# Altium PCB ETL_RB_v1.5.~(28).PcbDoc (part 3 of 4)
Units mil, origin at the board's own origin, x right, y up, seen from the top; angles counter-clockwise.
Board outline 5129.92 x 2224.41 mil, 8 copper layers (Top Layer, plane 1, M1, plane 2, plane 3, M2, plane 4, Bottom Layer), stack 36.907 mil thick; 212 components, 186 nets, 1961 pads, 978 vias.
Unrouted connection lines stored in the file: 395.
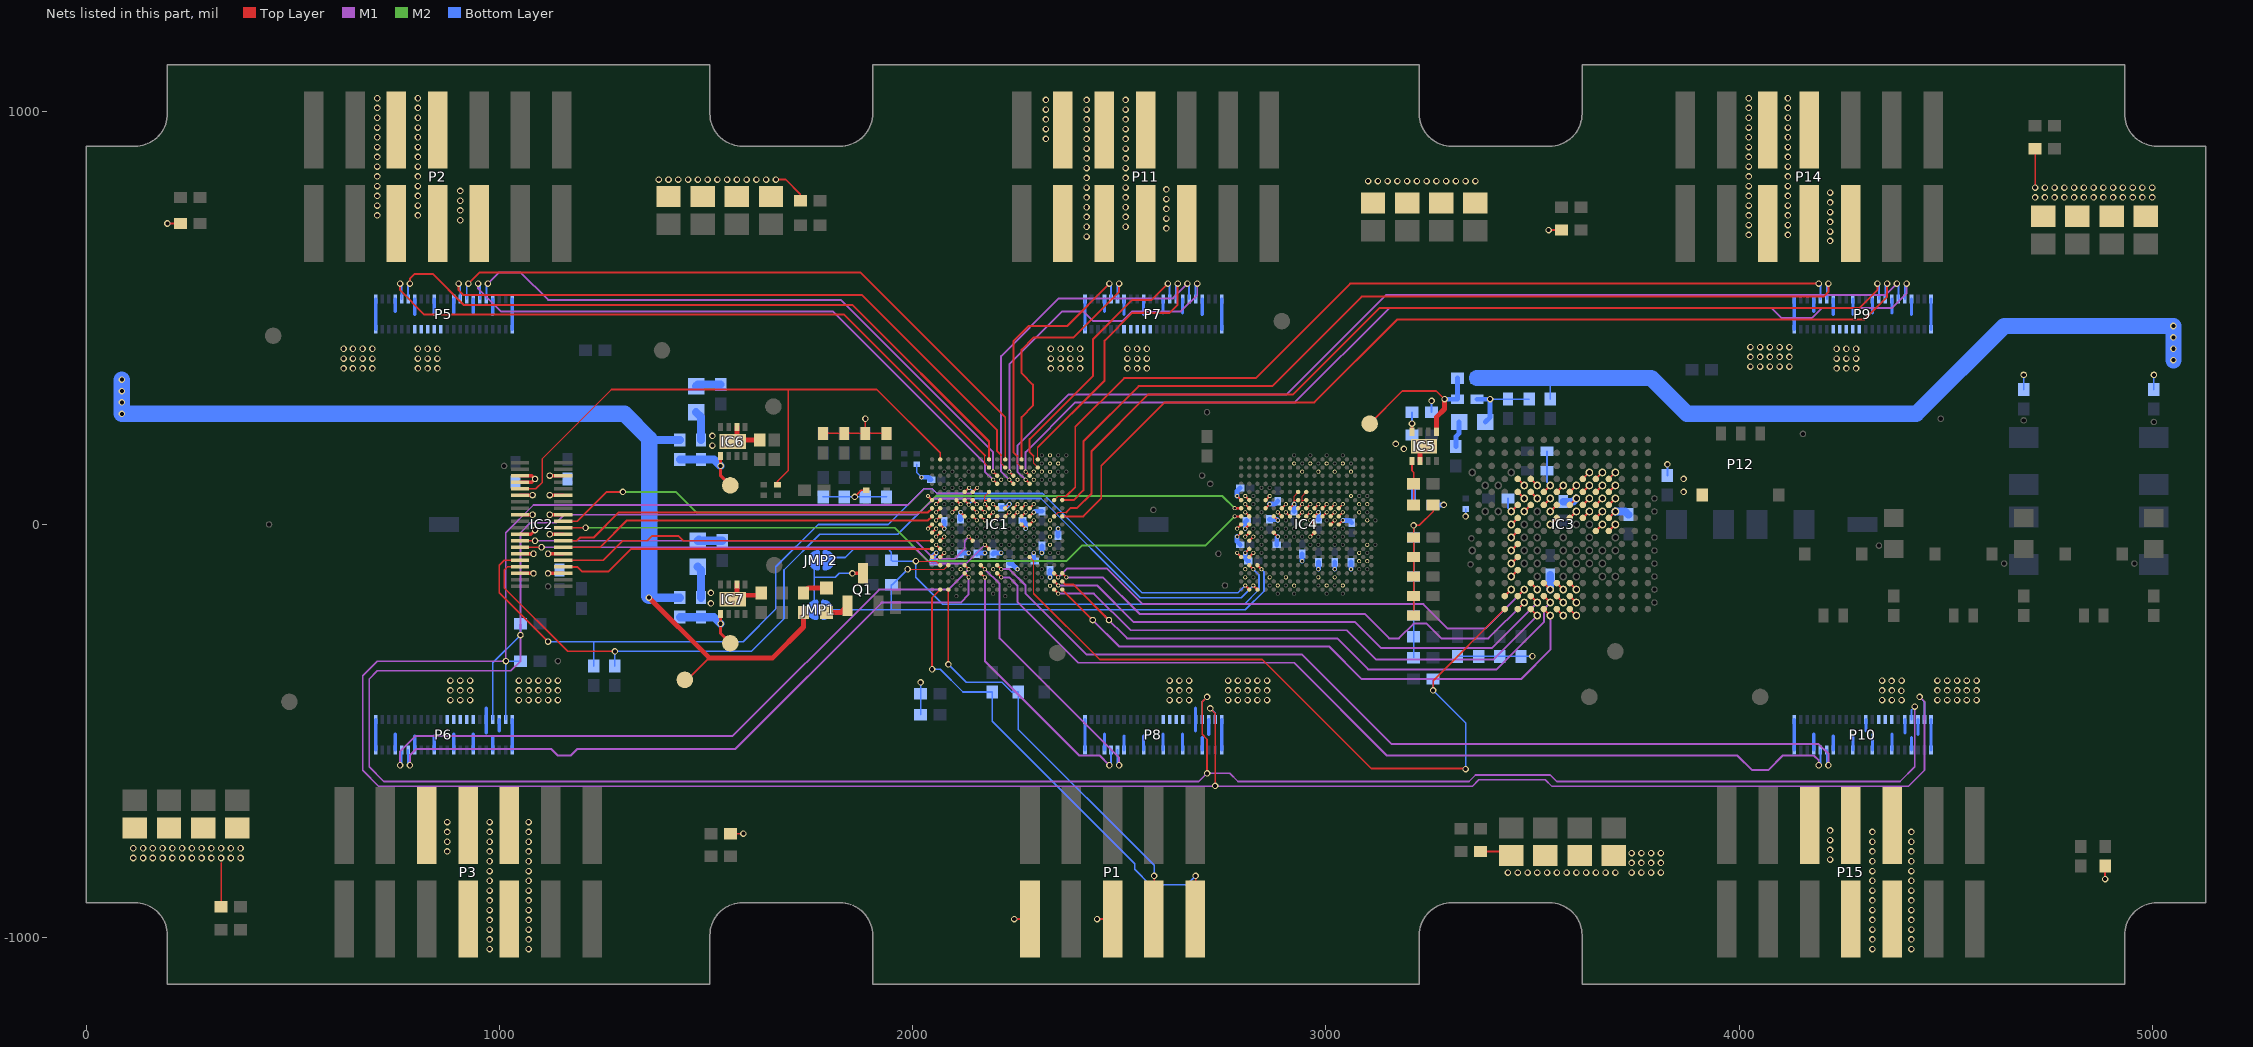
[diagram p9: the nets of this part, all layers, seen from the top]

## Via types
v1: diameter 15.75, hole 9.84, Top Layer to Bottom Layer, 978 vias

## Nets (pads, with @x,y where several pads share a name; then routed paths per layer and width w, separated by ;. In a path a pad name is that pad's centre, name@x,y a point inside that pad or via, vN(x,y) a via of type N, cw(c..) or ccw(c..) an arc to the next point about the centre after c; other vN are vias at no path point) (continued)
EDIN30N: IC1.H17 P9.34 | length 2332.9
  Top Layer w4.72: IC1.H17@2362.2,19.69 2413.39,19.68 2456.69,62.99 2456.69,141.73 2610.24,295.28 2972.44,295.28 3173.23,496.06 4303.15,496.06 4358.27,551.18 v1(4358.27,582.68)
  Bottom Layer w4.72: P9.34@4354.33,545.28 4354.33,578.74 v1(4358.27,582.68)
EDIN30P: IC1.H16 P9.33 | length 2333.5
  Top Layer w3: IC1.H16@2342.52,19.69 2352.36,29.53 2372.05,29.53
  Top Layer w4.72: 2372.05,29.53 2381.89,39.37 2397.64,39.37 2433.07,74.8 2433.07,177.17 2570.87,314.96 2921.26,314.96 3129.92,523.62 4291.34,523.62 4334.65,566.93 v1(4334.65,582.68)
  Bottom Layer w4.72: v1(4334.65,582.68) 4338.58,578.74 P9.33@4338.58,545.28
EDIN32N: IC1.F17 P9.25 | length 2191
  Top Layer w4.72: IC1.F17@2362.2,59.06 2389.76,59.06 2413.39,82.68 2413.39,200.79 2547.24,334.65 2870.08,334.65 3086.61,551.18 4204.72,551.18 4216.54,562.99 v1(4216.54,582.68)
  Bottom Layer w4.72: P9.25@4212.6,545.28 4212.6,578.74 v1(4216.54,582.68)
EDIN32P: IC1.F16 P9.24 | length 2191.6
  Top Layer w3: IC1.F16@2342.52,59.06 2352.36,68.9 2372.05,68.9
  Top Layer w4.72: 2372.05,68.9 2393.7,90.55 2393.7,236.22 2511.81,354.33 2830.71,354.33 3059.06,582.68 v1(4192.91,582.68)
  Bottom Layer w4.72: v1(4192.91,582.68) 4196.85,578.74 P9.24@4196.85,545.28
EDIN40N: IC1.A14 P7.34 | length 657.5
  Top Layer w3: IC1.A14@2303.15,157.48 2303.15,187.01
  Top Layer w4.72: 2303.15,187.01 2464.57,348.43 2464.57,444.88 2531.5,511.81 2622.05,511.81 2641.73,531.5 v1(2641.73,582.68)
  Bottom Layer w4.72: P7.34@2637.8,545.28 2637.8,578.74 v1(2641.73,582.68)
EDIN40P: IC1.B14 P7.33 | length 658.4
  Top Layer w3: 2293.31,165.35 2293.31,147.64 IC1.B14@2303.15,137.8
  Top Layer w4.72: 2293.31,165.35 2283.46,175.2 2283.46,206.69 2437.01,360.24 2437.01,448.82 2531.5,543.31 2578.74,543.31 v1(2618.11,582.68)
  Bottom Layer w4.72: v1(2618.11,582.68) 2622.05,578.74 P7.33@2622.05,545.28
EDIN42N: IC1.A12 P7.25 | length 641.4
  Top Layer w4.72: IC1.A12@2263.78,157.48 2263.78,259.84 2291.34,287.4 2291.34,338.58 2263.78,366.14 2263.78,423.23 2293.31,452.76 2389.76,452.76 2500,562.99 v1(2500,582.68)
  Bottom Layer w4.72: P7.25@2496.06,545.28 2496.06,578.74 v1(2500,582.68)
EDIN42P: IC1.B12 P7.24 | length 642.5
  Top Layer w3: 2253.94,165.35 2253.94,147.64 IC1.B12@2263.78,137.8
  Top Layer w4.72: 2253.94,165.35 2244.09,175.2 2244.09,442.91 2281.5,480.32 2374.02,480.32 v1(2476.38,582.68)
  Bottom Layer w4.72: v1(2476.38,582.68) 2480.31,578.74 P7.24@2480.31,545.28
EDIN50N: IC1.A10 P5.34 | length 1597.2
  Top Layer w4.72: v1(925.2,582.68) 952.76,610.24 1874.02,610.24 2224.41,259.84 IC1.A10@2224.41,157.48
  Bottom Layer w4.72: P5.34@921.26,545.28 921.26,578.74 v1(925.2,582.68)
EDIN50P: IC1.B10 P5.33 | length 1596.9
  Top Layer w3: 2214.57,167.32 2214.57,147.64 IC1.B10@2224.41,137.8
  Top Layer w4.72: v1(901.57,582.68) 901.57,566.93 913.39,555.12 1877.95,555.12 2204.72,228.35 2204.72,177.17 2214.57,167.32
  Bottom Layer w4.72: v1(901.57,582.68) 905.51,578.74 P5.33@905.51,545.28
EDIN52N: IC1.A8 P5.25 | length 1668.6
  Top Layer w4.72: v1(783.46,582.68) 783.46,594.49 795.28,606.3 838.58,606.3 913.39,531.5 1854.33,531.5 2185.04,200.79 IC1.A8@2185.04,157.48
  Bottom Layer w4.72: P5.25@779.53,545.28 779.53,578.74 v1(783.46,582.68)
EDIN52P: IC1.B8 P5.24 | length 1669.3
  Top Layer w3: 2175.2,167.32 2175.2,147.64 IC1.B8@2185.04,137.8
  Top Layer w4.72: v1(759.84,582.68) 759.84,566.93 818.9,507.87 1834.65,507.87 2175.2,167.32
  Bottom Layer w4.72: v1(759.84,582.68) 763.78,578.74 P5.24@763.78,545.28
EDOUT00N: IC1.R5 P6.36 pad.1@2135.83,-127.95 | length 1644.8
  Top Layer w5.12: IC1.R5@2125.98,-118.11 pad.1@2135.83,-127.95
  M1 w4.72: v1(783.46,-582.68) 783.46,-559.06 799.21,-543.31 1125.98,-543.31 1141.73,-559.06 1173.23,-559.06 1188.98,-543.31 1570.87,-543.31 1925.2,-188.98 2116.14,-188.98 2135.83,-169.29 pad.1@2135.83,-127.95
  Bottom Layer w4.72: P6.36@779.53,-545.28 779.53,-578.74 v1(783.46,-582.68)
EDOUT00P: IC1.P5 P6.37 pad.1@2135.83,-108.27 | length 1645
  Top Layer w5.12: IC1.P5@2125.98,-98.42 pad.1@2135.83,-108.27
  M1 w4.72: v1(759.84,-582.68) 759.84,-549.21 797.24,-511.81 1564.96,-511.81 1919.29,-157.48 2086.61,-157.48 pad.1@2135.83,-108.27
  Bottom Layer w4.72: v1(759.84,-582.68) 763.78,-578.74 P6.37@763.78,-545.28
EDOUT02N: IC1.R7 P8.37 pad.1@2175.2,-127.95 | length 661.3
  Top Layer w5.12: IC1.R7@2165.35,-118.11 pad.1@2175.2,-127.95
  M1 w5.12: pad.1@2175.2,-127.95 2175.2,-330.71 2403.54,-559.06 2452.76,-559.06 v1(2476.38,-582.68)
  Bottom Layer w4.72: v1(2476.38,-582.68) 2480.31,-578.74 P8.37@2480.31,-545.28
EDOUT02P: IC1.P7 P8.36 pad.1@2175.2,-108.27 | length 661.9
  Top Layer w5.12: IC1.P7@2165.35,-98.42 pad.1@2175.2,-108.27
  M1 w4.72: pad.1@2175.2,-108.27 2210.63,-143.7 2210.63,-275.59 2468.5,-533.46 2500,-564.96 v1(2500,-582.68)
  Bottom Layer w4.72: P8.36@2496.06,-545.28 2496.06,-578.74 v1(2500,-582.68)
EDOUT10N: IC1.R9 P10.37 pad.1@2214.57,-127.95 | length 2279
  Top Layer w5.12: IC1.R9@2204.72,-118.11 pad.1@2214.57,-127.95
  M1 w4.72: pad.1@2214.57,-127.95 2234.25,-127.95 2253.94,-147.64 2253.94,-187.01 2401.57,-334.65 2923.23,-334.65 3147.64,-559.06 3996.06,-559.06 4031.5,-594.49 4070.87,-594.49 4106.3,-559.06 4181.1,-559.06 4192.91,-570.87 v1(4192.91,-582.68)
  Bottom Layer w4.72: v1(4192.91,-582.68) 4196.85,-578.74 P10.37@4196.85,-545.28
EDOUT10P: IC1.P9 P10.36 pad.1@2214.57,-108.27 | length 2279.1
  Top Layer w5.12: IC1.P9@2204.72,-98.42 pad.1@2214.57,-108.27
  M1 w4.72: pad.1@2214.57,-108.27 2234.25,-108.27 2273.62,-147.64 2273.62,-167.32 2421.26,-314.96 2942.91,-314.96 3159.45,-531.5 4192.91,-531.5 4216.54,-555.12 v1(4216.54,-582.68)
  Bottom Layer w4.72: P10.36@4212.6,-545.28 4212.6,-578.74 v1(4216.54,-582.68)
EDOUT20N: IC1.C13 P9.37 pad.1@2273.62,127.95 | length 2434.3
  Top Layer w5.12: pad.1@2273.62,127.95 IC1.C13@2283.46,118.11
  M1 w4.72: pad.1@2273.62,127.95 2273.62,175.2 2393.7,295.28 2925.2,295.28 3153.54,523.62 4078.74,523.62 4102.36,500 4177.17,500 4200.79,523.62 4370.08,523.62 4405.51,559.06 v1(4405.51,582.68)
  Bottom Layer w4.72: P9.37@4401.57,545.28 4401.57,578.74 v1(4405.51,582.68)
EDOUT20P: IC1.D13 P9.36 pad.1@2273.62,108.27 | length 2434
  Top Layer w5.12: pad.1@2273.62,108.27 IC1.D13@2283.46,98.43
  M1 w4.72: pad.1@2273.62,108.27 2253.94,127.95 2253.94,190.94 2377.95,314.96 2905.51,314.96 3145.67,555.12 4354.33,555.12 v1(4381.89,582.68)
  Bottom Layer w4.72: v1(4381.89,582.68) 4385.83,578.74 P9.36@4385.83,545.28
EDOUT22N: IC1.C11 P7.37 pad.1@2234.25,127.95 | length 884
  Top Layer w5.12: pad.1@2234.25,127.95 IC1.C11@2244.09,118.11
  M1 w4.72: pad.1@2234.25,127.95 2234.25,387.79 2362.2,515.75 2413.39,515.75 2437.01,492.13 2507.87,492.13 2531.5,515.75 2649.61,515.75 2688.98,555.12 v1(2688.98,582.68)
  Bottom Layer w4.72: P7.37@2685.04,545.28 2685.04,578.74 v1(2688.98,582.68)
EDOUT22P: IC1.D11 P7.36 pad.1@2234.25,108.27 | length 883.7
  Top Layer w5.12: pad.1@2234.25,108.27 IC1.D11@2244.09,98.43
  M1 w4.72: pad.1@2234.25,108.27 2214.57,127.95 2214.57,407.48 2354.33,547.24 2629.92,547.24 v1(2665.35,582.68)
  Bottom Layer w4.72: v1(2665.35,582.68) 2669.29,578.74 P7.36@2669.29,545.28
EDOUT30N: IC1.C9 P5.37 pad.1@2194.88,127.95 | length 1514.3
  Top Layer w5.12: pad.1@2194.88,127.95 IC1.C9@2204.72,118.11
  M1 w4.72: v1(972.44,582.68) 1000,610.24 1051.18,610.24 1118.11,543.31 1826.77,543.31 2194.88,175.2 pad.1@2194.88,127.95
  Bottom Layer w4.72: P5.37@968.5,545.28 968.5,578.74 v1(972.44,582.68)
EDOUT30P: IC1.D9 P5.36 pad.1@2194.88,108.27 | length 1514
  Top Layer w5.12: pad.1@2194.88,108.27 IC1.D9@2204.72,98.43
  M1 w4.72: v1(948.82,582.68) 948.82,570.87 1003.94,515.75 1807.09,515.75 2175.2,147.64 2175.2,127.95 pad.1@2194.88,108.27
  Bottom Layer w4.72: v1(948.82,582.68) 952.76,578.74 P5.36@952.76,545.28
GBT_RESET_B: IC1.N13 IC3.M14 R107.2 | length 1833.8
  Top Layer w3: IC1.N13@2283.46,-78.74 2293.31,-88.58 2293.31,-167.32
  Top Layer w4: 2293.31,-167.32 2452.76,-326.77 2846.46,-326.77 3110.24,-590.55 3338.58,-590.55 v1(3338.58,-591.98) ; v1(3259.84,-401.57) 3259.84,-377.95 IC3.M14@3433.07,-204.72
  Bottom Layer w4: R107.2@3259.84,-374.02 v1(3259.84,-401.57) 3338.58,-480.32 v1(3338.58,-591.98)
GND: C105.2 C106.2 C107.2 C108.2 C109.2 C111.2 C112.2 C113.2 C114.2 C115.2 C116.2 C117.2 C118.2 C119.2 C120.2 C121.2 C122.2 C123.2 C124.2 C125.2 C126.2 C127.2 C128.2 C129.2 C130.2 C131.2 C132.2 C133.2 C134.2 C135.2 C136.2 C138.2 C139.2 C140.2 C141.2 C150.2 C151.2 C152.2 C153.2 C154.2 C155.2 C160.2 C162.2 C163.2 C164.2 C165.2 C166.2 C167.2 C168.2 C169.2 C201.1 C202.1 C203.1 C204.1 C205.1 C206.1 C207.1 C208.1 C209.1 C210.1 C211.1 C212.1 C213.1 C214.1 C218.2 C219.2 C220.2 C221.2 C222.2 C223.2 C224.2 C225.2 C226.2 C227.2 C228.2 C229.2 C230.2 C231.2 C232.2 C233.2 IC1.E8 IC1.F1 IC1.F2 IC1.F4 IC1.F8 IC1.G2 IC1.G4 IC1.G6 IC1.G7 IC1.G8 IC1.G9 IC1.G10 IC1.G11 IC1.G12 IC1.G13 IC1.H2 IC1.H5 IC1.H6 IC1.H7 IC1.H8 IC1.H9 IC1.H10 IC1.H11 IC1.H12 IC1.H13 IC1.J1 IC1.J2 IC1.J12 IC1.J13 IC1.K1 IC1.K2 IC1.L2 IC1.M2 IC1.N1 IC1.N2 IC2.5 IC2.6 IC2.11 IC2.12 IC2.17 IC2.18 IC2.23 IC2.24 IC2.29 IC2.30 IC2.34 IC2.35 IC2.36 IC3.D4 IC3.D5 IC3.D6 IC3.D7 IC3.D8 IC3.E4 IC3.E5 IC3.E6 IC3.E7 IC3.E8 IC3.F4 IC3.F5 IC3.F6 IC3.F7 IC3.G5 IC3.G6 IC3.G7 IC3.G12 IC3.G13 IC3.G14 IC3.H5 IC3.H6 IC3.H7 IC3.H12 IC3.H13 IC3.H14 IC3.J5 IC3.J6 IC3.J12 IC3.K4 IC3.K5 IC3.K6 IC3.K12 IC3.L4 IC3.L5 IC3.L6 IC3.L7 IC3.L8 IC3.L9 IC3.L10 IC3.L11 IC3.M13 IC4.E8 IC4.E9 IC4.F1 IC4.F2 IC4.F4 IC4.F8 IC4.F9 IC4.G2 IC4.G4 IC4.G6 IC4.G7 IC4.G8 IC4.G9 IC4.G10 IC4.G11 IC4.G12 IC4.G13 IC4.H2 IC4.H5 IC4.H6 IC4.H7 IC4.H8 IC4.H9 IC4.H10 IC4.H11 IC4.H12 IC4.H13 IC4.J1 IC4.J2 IC4.J10 IC4.J12 IC4.J13 IC4.K1 IC4.K2 IC4.K5 IC4.K10 IC4.L2 IC4.M2 IC4.N1 IC4.N2 IC5.6 IC5.9 IC6.6 IC6.9 IC7.6 IC7.9 JMP1.1 JMP2.1 P1.6 P1.10 P2.5 P2.6 P2.7 P2.8 P2.9 P3.5 P3.6 P3.7 P3.8 P3.9 P5.11 P5.12 P5.13 P5.14 P5.15 P5.23 P5.26 P5.29 P5.32 P5.35 P5.38 P5.41 P5.42 P5.43 P5.44 P6.11 P6.12 P6.13 P6.14 P6.15 P6.17 P6.19 P6.23 P6.26 P6.29 P6.32 P6.35 P6.38 P6.41 P6.42 P6.43 P6.44 P7.11 P7.12 P7.13 P7.14 P7.15 P7.23 P7.26 P7.29 P7.32 P7.35 P7.38 P7.41 P7.42 P7.43 P7.44 P8.12 P8.13 P8.14 P8.15 P8.17 P8.19 P8.23 P8.26 P8.29 P8.32 P8.35 P8.38 P8.41 P8.42 P8.43 P8.44 P9.11 P9.12 P9.13 P9.14 P9.15 P9.23 P9.26 P9.29 P9.32 P9.35 P9.38 P9.41 P9.42 P9.43 P9.44 P10.11 P10.13 P10.14 P10.15 P10.17 P10.19 P10.23 P10.26 P10.29 P10.32 P10.35 P10.38 P10.41 P10.42 P10.43 P10.44 P11.5 P11.6 P11.7 P11.8 P11.9 P12.4 P14.5 P14.6 P14.7 P14.8 P14.9 P15.5 P15.6 P15.7 P15.8 P15.9 pad.1@1080.71,23.62 pad.1@1080.71,70.87 pad.1@1082.68,-70.87 pad.1@1082.68,-118.11 pad.1@1086.61,110.24 pad.1@1086.61,-13.78 pad.1@1118.11,-70.87 pad.1@1118.11,-118.11 pad.1@1122.05,23.62 pad.1@1122.05,70.87 pad.1@1122.05,118.11 pad.1@1122.05,-23.62 pad.1@2021.65,114.17 pad.1@2037.4,68.9 pad.1@2037.4,-9.84 pad.1@2057.09,9.84 pad.1@2057.09,29.53 pad.1@2057.09,49.21 pad.1@2057.09,-9.84 pad.1@2057.09,-29.53 pad.1@2057.09,-49.21 pad.1@2057.09,-68.9 pad.1@2076.77,-9.84 pad.1@2076.77,-29.53 pad.1@2076.77,-68.9 pad.1@2096.46,29.53 pad.1@2116.14,29.53 pad.1@2116.14,49.21 pad.1@2116.14,-108.27 pad.1@2135.83,-68.9 pad.1@2155.51,9.84 pad.1@2155.51,29.53 pad.1@2175.2,9.84 pad.1@2175.2,29.53 pad.1@2175.2,49.21 pad.1@2175.2,-68.9 pad.1@2194.88,9.84 pad.1@2194.88,29.53 pad.1@2194.88,49.21 pad.1@2194.88,-108.27 pad.1@2214.57,108.27 pad.1@2214.57,-68.9 pad.1@2234.25,29.53 pad.1@2234.25,49.21 pad.1@2253.94,29.53 pad.1@2253.94,49.21 pad.1@2253.94,108.27 pad.1@2253.94,-108.27 pad.1@2273.62,29.53 pad.1@2273.62,49.21 pad.1@2273.62,-9.84 pad.1@2293.31,9.84 pad.1@2293.31,29.53 pad.1@2293.31,49.21 pad.1@2293.31,108.27 pad.1@2293.31,127.95 pad.1@2293.31,-68.9 pad.1@2312.99,127.95 pad.1@2312.99,-68.9 pad.1@2332.58,-148.45 pad.1@2332.59,127.48 pad.1@2332.68,9.84 pad.1@2332.68,147.64 pad.1@2332.68,167.32 pad.1@2332.68,-9.84 pad.1@2332.68,-29.53 pad.1@2332.68,-49.21 pad.1@2332.68,-127.95 pad.1@2352.36,147.64 pad.1@2352.36,-9.84 pad.1@2785.43,68.9 pad.1@2785.43,-9.84 pad.1@2785.43,-29.53 pad.1@2785.43,-68.9 pad.1@2805.12,29.53 pad.1@2805.12,49.21 pad.1@2805.12,68.9 pad.1@2805.12,-9.84 pad.1@2805.12,-29.53 pad.1@2805.12,-68.9 pad.1@2805.12,-108.27 pad.1@2805.12,-127.95 pad.1@2824.8,-29.53 pad.1@2824.8,-68.9 pad.1@2864.17,49.21 pad.1@2864.17,68.9 pad.1@2864.17,-127.95 pad.1@2883.86,9.84 pad.1@2883.86,29.53 pad.1@2883.86,-29.53 pad.1@2883.86,-147.64 pad.1@2903.54,29.53 pad.1@2903.54,49.21 pad.1@2903.54,-127.95 pad.1@2923.23,49.21 pad.1@2923.23,147.64 pad.1@2923.44,-147.82 pad.1@2942.91,29.53 pad.1@2942.91,49.21 pad.1@2942.91,127.95 pad.1@2942.91,-88.58 pad.1@2962.6,9.84 pad.1@2962.6,29.53 pad.1@2962.6,49.21 pad.1@2962.6,147.64 pad.1@2962.6,-29.53 pad.1@2982.28,29.53 pad.1@2982.28,49.21 pad.1@2982.28,127.95 pad.1@2982.28,-108.27 pad.1@2982.28,-127.95 pad.1@3001.97,29.53 pad.1@3001.97,49.21 pad.1@3001.97,147.64 pad.1@3001.97,-147.64 pad.1@3021.65,9.84 pad.1@3021.65,29.53 pad.1@3021.65,49.21 pad.1@3021.65,127.95 pad.1@3021.65,-108.27 pad.1@3021.65,-127.95 pad.1@3041.34,9.84 pad.1@3041.34,29.53 pad.1@3041.34,49.21 pad.1@3041.34,147.64 pad.1@3041.34,-147.64 pad.1@3061.02,68.9 pad.1@3061.02,127.95 pad.1@3061.02,-108.27 pad.1@3080.71,29.53 pad.1@3080.71,49.21 pad.1@3080.71,-68.9 pad.1@3080.71,-88.58 pad.1@3100.39,9.84 pad.1@3100.39,49.21 pad.1@3100.39,-49.21 pad.1@3100.39,-88.58 pad.1@3448.82,0 pad.1@3448.82,31.5 pad.1@3448.82,-31.5 pad.1@3448.82,-62.99 pad.1@3448.82,-94.49 pad.1@3448.82,-125.98 pad.1@3448.82,-157.48 pad.1@3480.31,31.5 pad.1@3480.31,62.99 pad.1@3480.31,94.49 pad.1@3511.81,62.99 pad.1@3511.81,94.49 pad.1@3511.81,-157.48 pad.1@3543.31,0 pad.1@3543.31,31.5 pad.1@3543.31,62.99 pad.1@3543.31,94.49 pad.1@3543.31,-157.48 pad.1@3574.8,94.49 pad.1@3574.8,-157.48 pad.1@3574.8,-188.98 pad.1@3574.8,-220.47 pad.1@3606.3,31.5 pad.1@3606.3,62.99 pad.1@3606.3,94.49 pad.1@3606.3,-157.48 pad.1@3606.3,-188.98 pad.1@3606.3,-220.47 pad.1@3637.8,31.5 pad.1@3637.8,62.99 pad.1@3637.8,94.49 pad.1@3637.8,125.98 pad.1@3669.29,0 pad.1@3669.29,31.5 pad.1@3669.29,62.99 pad.1@3669.29,94.49 pad.1@3669.29,125.98 pad.1@3700.79,0 pad.1@3700.79,31.5 pad.1@3700.79,62.99 pad.1@3700.79,94.49 pad.1@3700.79,125.98 pad.1@4688.98,362.2 pad.1@5003.94,362.2 Q1.3 R112.2 R115.2 R118.1 R120.1 R122.1 R123.2 R126.2 R132.2 R134.1 R143.1 R146.1 R203.1 R205.1 R207.1 R209.1 R211.1 R213.1 R215.1 R217.1 R219.1 R221.1 R223.1 R225.1 R227.1 R229.1 R233.2 R234.2 R235.2 R236.2 RT1.1 RT2.1 | length 8528
  Top Layer w3: pad.1@2175.2,49.21 2175.2,59.06 ; IC1.F8@2185.04,59.06 2175.2,59.06 ; IC1.E8@2185.04,78.74 2175.2,68.9 2175.2,59.06 ; pad.1@2923.23,49.21 2923.23,59.06 ; IC4.F8@2933.07,59.05 2923.23,59.06 ; IC4.E8@2933.07,78.74 2923.23,68.9 2923.23,59.06 ; pad.1@2942.91,49.21 2942.91,59.05 ; IC4.F9@2952.76,59.05 2942.91,59.05 ; IC4.E9@2952.76,78.74 2942.91,68.9 2942.91,59.05
  Top Layer w4: v1(196.85,728.35) R233.2@228.35,728.35 ; R217.1@326.77,-925.2 326.77,-818.9 ; R234.2@1559.06,-748.03 v1(1590.55,-748.03) ; v1(1669.29,834.65) 1692.91,834.65 1728.35,799.21 R215.1@1728.35,783.46 ; C151.2@1783.46,220.47 C150.2@1834.65,220.47 C109.2@1885.83,220.47 ; v1(1860.24,66.93) 1875.98,82.68 RT1.1@1887.8,82.68 ; v1(1885.83,255.91) C109.2@1885.83,220.47 ; C141.2@1937.01,220.47 C109.2@1885.83,220.47 ; v1(2246.06,-954.72) 2248.03,-954.72 P1.10@2284.25,-954.72 ; v1@2448.82,-954.72 v1(2446.85,-954.72) P1.6@2484.25,-954.72 ; C201.1@3212.6,-220.47 C203.1@3212.6,-173.23 C205.1@3212.6,-125.98 C207.1@3212.6,-78.74 C210.1@3212.6,-31.5 ; R221.1@3374.02,-791.34 3438.98,-791.34 C233.2@3448.82,-801.18 ; v1(3539.37,712.6) R235.2@3570.87,712.6 ; v1(4716.54,814.96) R219.1@4716.54,909.45 ; v1(4885.83,-858.27) R236.2@4885.83,-826.77
  Top Layer w4.02: C210.1@3212.6,-31.5 v1(3212.6,-1.97) 3226.38,-1.97 3259.84,31.5 R112.2@3259.84,47.24
  Top Layer w5.12: pad.1@2037.4,-9.84 IC1.J1@2047.24,0 ; pad.1@2037.4,68.9 IC1.F1@2047.24,59.06 ; IC1.N1@2047.24,-78.74 pad.1@2057.09,-68.9 ; IC1.K1@2047.24,-19.68 pad.1@2057.09,-9.84 ; pad.1@2057.09,-49.21 IC1.M2@2066.93,-59.05 ; pad.1@2057.09,-29.53 IC1.K2@2066.93,-19.68 ; pad.1@2057.09,9.84 IC1.H2@2066.93,19.69 ; pad.1@2057.09,29.53 IC1.G2@2066.93,39.37 ; pad.1@2057.09,49.21 IC1.F2@2066.93,59.06 ; IC1.N2@2066.93,-78.74 pad.1@2076.77,-68.9 ; IC1.L2@2066.93,-39.37 pad.1@2076.77,-29.53 ; IC1.J2@2066.93,0 pad.1@2076.77,-9.84 ; pad.1@2096.46,29.53 IC1.G4@2106.3,39.37 ; IC1.F4@2106.3,59.06 pad.1@2116.14,49.21 ; pad.1@2116.14,29.53 IC1.H5@2125.98,19.69 ; IC1.H6@2145.67,19.69 pad.1@2155.51,9.84 ; IC1.G6@2145.67,39.37 pad.1@2155.51,29.53 ; IC1.H7@2165.35,19.69 pad.1@2175.2,9.84 ; IC1.G7@2165.35,39.37 pad.1@2175.2,29.53 ; pad.1@2175.2,49.21 IC1.G8@2185.04,39.37 ; IC1.H8@2185.04,19.69 pad.1@2194.88,29.53 ; pad.1@2194.88,9.84 IC1.H9@2204.72,19.69 ; pad.1@2194.88,49.21 IC1.G9@2204.72,39.37 ; IC1.H10@2224.41,19.69 pad.1@2234.25,29.53 ; IC1.G10@2224.41,39.37 pad.1@2234.25,49.21 ; IC1.H11@2244.09,19.69 pad.1@2253.94,29.53 ; IC1.G11@2244.09,39.37 pad.1@2253.94,49.21 ; IC1.J12@2263.78,0 pad.1@2273.62,-9.84 ; IC1.H12@2263.78,19.69 pad.1@2273.62,29.53 ; IC1.G12@2263.78,39.37 pad.1@2273.62,49.21 ; IC1.J13@2283.46,0 pad.1@2293.31,9.84 ; IC1.H13@2283.46,19.69 pad.1@2293.31,29.53 ; IC1.G13@2283.46,39.37 pad.1@2293.31,49.21 ; pad.1@2785.43,-68.9 IC4.N1@2795.28,-78.74 ; pad.1@2785.43,-29.53 IC4.K1@2795.28,-19.68 ; pad.1@2785.43,-9.84 IC4.J1@2795.28,0 ; pad.1@2785.43,68.9 IC4.F1@2795.28,59.05 ; pad.1@2805.12,-68.9 IC4.M2@2814.96,-59.05 ; pad.1@2805.12,-29.53 IC4.K2@2814.96,-19.68 ; pad.1@2805.12,-9.84 IC4.J2@2814.96,0 ; pad.1@2805.12,29.53 IC4.H2@2814.96,19.68 ; pad.1@2805.12,49.21 IC4.G2@2814.96,39.37 ; pad.1@2805.12,68.9 IC4.F2@2814.96,59.05 ; IC4.N2@2814.96,-78.74 pad.1@2824.8,-68.9 ; IC4.L2@2814.96,-39.37 pad.1@2824.8,-29.53 ; IC4.G4@2854.33,39.37 pad.1@2864.17,49.21 ; IC4.F4@2854.33,59.05 pad.1@2864.17,68.9 ; IC4.K5@2874.02,-19.68 pad.1@2883.86,-29.53 ; IC4.H5@2874.02,19.68 pad.1@2883.86,9.84 ; pad.1@2883.86,29.53 IC4.H6@2893.7,19.68 ; IC4.G6@2893.7,39.37 pad.1@2903.54,49.21 ; pad.1@2903.54,29.53 IC4.H7@2913.39,19.68 ; IC4.G7@2913.39,39.37 pad.1@2923.23,49.21 ; IC4.H8@2933.07,19.68 pad.1@2942.91,29.53 ; IC4.G8@2933.07,39.37 pad.1@2942.91,49.21 ; IC4.H9@2952.76,19.68 pad.1@2962.6,29.53 ; IC4.G9@2952.76,39.37 pad.1@2962.6,49.21 ; pad.1@2962.6,-29.53 IC4.K10@2972.44,-19.68 ; pad.1@2962.6,9.84 IC4.J10@2972.44,0 ; IC4.H10@2972.44,19.68 pad.1@2982.28,29.53 ; IC4.G10@2972.44,39.37 pad.1@2982.28,49.21 ; IC4.H11@2992.13,19.68 pad.1@3001.97,29.53 ; IC4.G11@2992.13,39.37 pad.1@3001.97,49.21 ; IC4.J12@3011.81,0 pad.1@3021.65,9.84 ; IC4.H12@3011.81,19.68 pad.1@3021.65,29.53 ; IC4.G12@3011.81,39.37 pad.1@3021.65,49.21 ; IC4.J13@3031.5,0 pad.1@3041.34,9.84 ; IC4.H13@3031.5,19.68 pad.1@3041.34,29.53 ; IC4.G13@3031.5,39.37 pad.1@3041.34,49.21 ; IC3.M13@3433.07,-173.23 pad.1@3448.82,-157.48 ; pad.1@3448.82,-125.98 IC3.L11@3464.57,-110.24 ; pad.1@3448.82,-94.49 IC3.L10@3464.57,-78.74 ; pad.1@3448.82,-62.99 IC3.L9@3464.57,-47.24 ; pad.1@3448.82,-31.5 IC3.L8@3464.57,-15.75 ; pad.1@3448.82,0 IC3.L7@3464.57,15.75 ; pad.1@3448.82,31.5 IC3.L6@3464.57,47.24 ; IC3.L5@3464.57,78.74 pad.1@3480.31,62.99 ; IC3.L4@3464.57,110.24 pad.1@3480.31,94.49 ; pad.1@3480.31,31.5 IC3.K6@3496.06,47.24 ; IC3.K12@3496.06,-141.73 pad.1@3511.81,-157.48 ; IC3.K5@3496.06,78.74 pad.1@3511.81,62.99 ; IC3.K4@3496.06,110.24 pad.1@3511.81,94.49 ; IC3.J12@3527.56,-141.73 pad.1@3543.31,-157.48 ; IC3.J6@3527.56,47.24 pad.1@3543.31,62.99 ; IC3.J5@3527.56,78.74 pad.1@3543.31,94.49 ; pad.1@3543.31,0 IC3.H7@3559.05,15.75 ; pad.1@3543.31,31.5 IC3.H6@3559.05,47.24 ; IC3.H14@3559.05,-204.72 pad.1@3574.8,-220.47 ; IC3.H13@3559.05,-173.23 pad.1@3574.8,-188.98 ; IC3.H12@3559.05,-141.73 pad.1@3574.8,-157.48 ; IC3.H5@3559.05,78.74 pad.1@3574.8,94.49 ; IC3.G14@3590.55,-204.72 pad.1@3606.3,-220.47 ; IC3.G13@3590.55,-173.23 pad.1@3606.3,-188.98 ; IC3.G12@3590.55,-141.73 pad.1@3606.3,-157.48 ; IC3.G7@3590.55,15.75 pad.1@3606.3,31.5 ; IC3.G6@3590.55,47.24 pad.1@3606.3,62.99 ; IC3.G5@3590.55,78.74 pad.1@3606.3,94.49 ; IC3.F7@3622.05,15.75 pad.1@3637.8,31.5 ; IC3.F6@3622.05,47.24 pad.1@3637.8,62.99 ; IC3.F5@3622.05,78.74 pad.1@3637.8,94.49 ; IC3.F4@3622.05,110.24 pad.1@3637.8,125.98 ; IC3.E8@3653.54,-15.75 pad.1@3669.29,0 ; IC3.E7@3653.54,15.75 pad.1@3669.29,31.5 ; IC3.E6@3653.54,47.24 pad.1@3669.29,62.99 ; IC3.E5@3653.54,78.74 pad.1@3669.29,94.49 ; IC3.E4@3653.54,110.24 pad.1@3669.29,125.98 ; IC3.D8@3685.04,-15.75 pad.1@3700.79,0 ; IC3.D7@3685.04,15.75 pad.1@3700.79,31.5 ; IC3.D6@3685.04,47.24 pad.1@3700.79,62.99 ; IC3.D5@3685.04,78.74 pad.1@3700.79,94.49 ; IC3.D4@3685.04,110.24 pad.1@3700.79,125.98
  Top Layer w7.87: IC2.6@1050,-118.11 pad.1@1082.68,-118.11 ; IC2.12@1050,-70.87 pad.1@1082.68,-70.87 ; IC2.18@1050,-23.62 1076.77,-23.62 pad.1@1086.61,-13.78 ; IC2.24@1050,23.62 pad.1@1080.71,23.62 ; IC2.30@1050,70.87 pad.1@1080.71,70.87 ; IC2.34@1050,102.36 1078.74,102.36 pad.1@1086.61,110.24 1078.74,118.11 IC2.36@1050,118.11 ; pad.1@1118.11,-118.11 IC2.5@1154.72,-118.11 ; pad.1@1118.11,-70.87 IC2.11@1154.72,-70.87 ; pad.1@1122.05,-23.62 IC2.17@1154.72,-23.62 ; pad.1@1122.05,23.62 IC2.23@1154.72,23.62 ; pad.1@1122.05,70.87 IC2.29@1154.72,70.87 ; pad.1@1122.05,118.11 IC2.35@1154.72,118.11 ; v1(1854.33,-118.11) Q1.3@1879.92,-118.11
  Top Layer w11.81: IC7.9@1564.96,-181.1 IC7.9@1574.8,-171.26 ; IC7.6@1574.8,-145.67 IC7.9@1574.8,-171.26 ; IC6.6@1574.8,236.22 1574.8,210.63 1569.88,205.71 1570.87,204.72 R115.2@1629.92,204.72 ; R123.2@1633.86,-165.35 1635.83,-165.35 1629.92,-171.26 IC7.9@1574.8,-171.26 ; IC5.6@3228.35,153.54 3228.35,179.13 IC5.9@3238.19,188.98
  Bottom Layer w4: 1761.81,-93.14 1761.81,-96.46 1761.81,-103.66 1761.81,-127.95 ; 1767.72,-194.88 1761.81,-188.98 1761.81,-187.91 1761.81,-127.95 ; R122.1@1783.46,66.93 R120.1@1834.65,66.93 R118.1@1885.83,66.93 R134.1@1937.01,66.93 ; v1(1854.33,-118.11) 1822.83,-118.11 1812.99,-127.95 1761.81,-127.95 ; R146.1@2009.84,145.67 2009.84,125.98 pad.1@2021.65,114.17 ; R132.2@2019.69,-460.63 v1(2019.69,-381.89) ; R203.1@3212.6,-322.83 R205.1@3212.6,-271.65 C202.1@3212.6,-220.47 C204.1@3212.6,-173.23 C206.1@3212.6,-125.98 C209.1@3212.6,-78.74 C208.1@3212.6,-31.5 ; R126.2@3255.91,271.65 v1(3255.91,299.21) ; R207.1@3318.9,-318.9 R209.1@3370.08,-318.9 R211.1@3421.26,-318.9 R213.1@3472.44,-318.9 v1(3500,-318.9) ; v1(3338.58,19.68) RT2.1@3338.58,37.4 ; v1(3397.64,303.15) C214.1@3440.94,303.15 R229.1@3492.13,303.15 ; C213.1@3535.43,177.17 C212.1@3535.43,129.92 3535.43,102.36 pad.1@3543.31,94.49
  Bottom Layer w4.02: C208.1@3212.6,-31.5 v1(3212.6,-1.97) ; C211.1@3440.94,62.99 3440.94,39.37 pad.1@3448.82,31.5 ; R227.1@3826.77,118.11 v1(3826.77,145.67) ; R225.1@4688.98,326.77 pad.1@4688.98,362.2 ; R223.1@5003.94,326.77 pad.1@5003.94,362.2
  Bottom Layer w7.87: P6.44@700.79,-545.28 P6.41@700.79,-472.44 ; P5.42@700.79,472.44 P5.43@700.79,545.28 ; P6.38@748.03,-545.28 748.03,-507.87 ; 748.03,515.75 P5.23@748.03,545.28 ; P6.35@795.28,-545.28 795.28,-511.81 ; 795.28,507.87 P5.26@795.28,545.28 ; P6.32@842.52,-545.28 842.52,-511.81 ; 842.52,507.87 P5.29@842.52,545.28 ; P6.29@889.76,-545.28 889.76,-507.87 ; 889.76,511.81 P5.32@889.76,545.28 ; P6.26@937.01,-545.28 937.01,-507.87 ; 937.01,511.81 P5.35@937.01,545.28 ; 968.5,-503.94 P6.17@968.5,-472.44 968.5,-444.88 ; P6.23@984.25,-545.28 984.25,-515.75 ; 984.25,507.87 P5.38@984.25,545.28 ; 1000,-500 P6.19@1000,-472.44 ; P6.43@1031.5,-545.28 P6.42@1031.5,-472.44 ; P5.41@1031.5,472.44 P5.44@1031.5,545.28 ; P8.44@2417.32,-545.28 P8.41@2417.32,-472.44 ; P7.42@2417.32,472.44 P7.43@2417.32,545.28 ; P8.38@2464.57,-545.28 2464.57,-507.87 ; 2464.57,515.75 P7.23@2464.57,545.28 ; P8.35@2511.81,-545.28 2511.81,-511.81 ; 2511.81,507.87 P7.26@2511.81,545.28 ; P8.32@2559.06,-545.28 2559.06,-511.81 ; 2559.06,507.87 P7.29@2559.06,545.28 ; P8.29@2606.3,-545.28 2606.3,-507.87 ; 2606.3,511.81 P7.32@2606.3,545.28 ; P8.26@2653.54,-545.28 2653.54,-507.87 ; 2653.54,511.81 P7.35@2653.54,545.28 ; 2685.04,-500 P8.17@2685.04,-472.44 2685.04,-444.88 ; P8.23@2700.79,-545.28 2700.79,-515.75 ; 2700.79,507.87 P7.38@2700.79,545.28 ; 2716.54,-507.87 P8.19@2716.54,-472.44 ; P8.43@2748.03,-545.28 P8.42@2748.03,-472.44 ; P7.41@2748.03,472.44 P7.44@2748.03,545.28 ; P10.44@4133.86,-545.28 P10.41@4133.86,-472.44 ; P9.42@4133.86,472.44 P9.43@4133.86,545.28 ; P10.38@4181.1,-545.28 4181.1,-507.87 ; 4181.1,515.75 P9.23@4181.1,545.28 ; P10.35@4228.35,-545.28 4228.35,-511.81 ; 4228.35,507.87 P9.26@4228.35,545.28 ; P10.32@4275.59,-545.28 4275.59,-511.81 ; 4275.59,507.87 P9.29@4275.59,545.28 ; 4307.09,-500 P10.11@4307.09,-472.44 ; P10.29@4322.83,-545.28 4322.83,-507.87 ; 4322.83,511.81 P9.32@4322.83,545.28 ; P10.26@4370.08,-545.28 4370.08,-507.87 ; 4370.08,511.81 P9.35@4370.08,545.28 ; 4401.57,-503.94 P10.17@4401.57,-472.44 ; P10.23@4417.32,-545.28 4417.32,-515.75 ; 4417.32,507.87 P9.38@4417.32,545.28 ; 4433.07,-507.87 P10.19@4433.07,-472.44 ; P10.43@4464.57,-545.28 P10.42@4464.57,-472.44 ; P9.41@4464.57,472.44 P9.44@4464.57,545.28
  Bottom Layer w11.81: pad.1@2021.65,114.17 2038.98,114.17 C119.2@2044.88,108.27 C119.2@2041.34,108.27 ; C125.2@2050.79,-90.55 2050.79,-75.2 pad.1@2057.09,-68.9 ; pad.1@2076.77,-9.84 C116.2@2076.77,7.48 ; C117.2@2116.14,-71.26 2118.5,-68.9 pad.1@2135.83,-68.9 ; C126.2@2116.14,12.2 pad.1@2116.14,29.53 ; C114.2@2155.51,-71.26 2157.87,-68.9 pad.1@2175.2,-68.9 ; C122.2@2194.88,-71.26 2197.24,-68.9 pad.1@2214.57,-68.9 ; C120.2@2214.57,41.73 2226.77,41.73 pad.1@2234.25,49.21 ; C118.2@2234.25,-94.88 2240.55,-94.88 pad.1@2253.94,-108.27 ; C136.2@2266.14,9.84 2273.62,2.36 pad.1@2273.62,-9.84 ; pad.1@2293.31,-68.9 2293.31,-86.22 C123.2@2295.67,-88.58 ; pad.1@2293.31,29.53 2295.67,31.89 C124.2@2312.99,31.89 ; pad.1@2312.99,-68.9 C115.2@2312.99,-51.57 ; pad.1@2332.68,-127.95 C121.2@2332.68,-110.63 ; C113.2@2352.36,-27.56 C113.2@2352.36,-27.17 pad.1@2352.36,-9.84 ; pad.1@2785.43,-29.53 2785.43,-41.73 C130.2@2792.91,-49.21 ; pad.1@2785.43,68.9 2785.43,81.1 C133.2@2792.91,88.58 ; pad.1@2805.12,-68.9 2805.12,-81.1 C132.2@2812.6,-88.58 ; pad.1@2805.12,-9.84 2805.12,6.3 C164.2@2808.66,9.84 ; C163.2@2864.17,12.2 2881.5,12.2 pad.1@2883.86,9.84 ; pad.1@2864.17,49.21 2876.38,49.21 C167.2@2883.86,56.69 ; C168.2@2881.5,-49.21 2881.5,-31.89 pad.1@2883.86,-29.53 ; pad.1@2923.23,49.21 C129.2@2923.23,31.89 C129.2@2923.62,31.5 ; pad.1@2942.91,-88.58 C128.2@2942.91,-71.26 ; pad.1@2982.28,-108.27 C134.2@2982.28,-90.94 ; C131.2@2982.28,12.2 pad.1@2982.28,29.53 ; pad.1@3021.65,-108.27 C165.2@3021.65,-90.94 ; pad.1@3041.34,9.84 3057.48,9.84 C166.2@3062.99,4.33 ; pad.1@3061.02,-108.27 C135.2@3061.02,-90.94 ; C155.2@3259.84,47.24 v1(3285.43,47.24) ; C105.2@3366.14,303.15 v1(3397.64,303.15) 3397.64,259.84 C107.2@3385.83,248.03
  Bottom Layer w18.9: pad.1@3543.31,-157.48 C138.2@3543.31,-122.05 ; C140.2@3574.8,55.12 3598.43,55.12 pad.1@3606.3,62.99 ; pad.1@3700.79,31.5 3724.41,31.5 C139.2@3732.28,23.62
  Bottom Layer w19.68: C108.2@1476.38,271.65 1488.19,259.84 C106.2@1488.19,204.72 ; C169.2@1480.31,-102.36 1488.19,-110.24 C152.2@1488.19,-177.17
  other v1: 976.38,-1027.56 1070.87,-1027.56 4322.83,-1027.56 4417.32,-1027.56 976.38,-1003.94 1070.87,-1003.94 4322.83,-1003.94 4417.32,-1003.94 976.38,-980.32 1070.87,-980.32 4322.83,-980.32 4417.32,-980.32 976.38,-956.69 1070.87,-956.69 4322.83,-956.69 4417.32,-956.69 976.38,-933.07 1070.87,-933.07 4322.83,-933.07 4417.32,-933.07 976.38,-909.45 1070.87,-909.45 4322.83,-909.45 4417.32,-909.45 976.38,-885.83 1070.87,-885.83 4322.83,-885.83 4417.32,-885.83 976.38,-862.2 1070.87,-862.2 4322.83,-862.2 4417.32,-862.2 3440.94,-842.52 3464.57,-842.52 3488.19,-842.52 3511.81,-842.52 3535.43,-842.52 3559.06,-842.52 3582.68,-842.52 3606.3,-842.52 3629.92,-842.52 3653.54,-842.52 3677.17,-842.52 3700.79,-842.52 3740.16,-842.52 3763.78,-842.52 3787.4,-842.52 3811.02,-842.52 976.38,-838.58 1070.87,-838.58 4322.83,-838.58 4417.32,-838.58 3740.16,-818.9 3763.78,-818.9 3787.4,-818.9 3811.02,-818.9 976.38,-814.96 1070.87,-814.96 4322.83,-814.96 4417.32,-814.96 4220.47,-811.02 114.17,-807.09 137.8,-807.09 161.42,-807.09 185.04,-807.09 208.66,-807.09 232.28,-807.09 255.91,-807.09 279.53,-807.09 303.15,-807.09 326.77,-807.09 350.39,-807.09 374.02,-807.09 3740.16,-795.28 3763.78,-795.28 3787.4,-795.28 3811.02,-795.28 874.02,-791.34 976.38,-791.34 1070.87,-791.34 4322.83,-791.34 4417.32,-791.34 4220.47,-787.4 114.17,-783.46 137.8,-783.46 161.42,-783.46 185.04,-783.46 208.66,-783.46 232.28,-783.46 255.91,-783.46 279.53,-783.46 303.15,-783.46 326.77,-783.46 350.39,-783.46 374.02,-783.46 874.02,-767.72 976.38,-767.72 1070.87,-767.72 4322.83,-767.72 4417.32,-767.72 4220.47,-763.78 874.02,-744.09 976.38,-744.09 1070.87,-744.09 4322.83,-744.09 4417.32,-744.09 4220.47,-740.16 874.02,-720.47 976.38,-720.47 1070.87,-720.47 881.89,-425.2 905.51,-425.2 929.13,-425.2 1047.24,-425.2 1070.87,-425.2 1094.49,-425.2 1118.11,-425.2 1141.73,-425.2 2622.05,-425.2 2645.67,-425.2 2669.29,-425.2 2763.78,-425.2 2787.4,-425.2 2811.02,-425.2 2834.65,-425.2 2858.27,-425.2 4346.46,-425.2 4370.08,-425.2 4393.7,-425.2 4480.32,-425.2 4503.94,-425.2 4527.56,-425.2 4551.18,-425.2 4574.8,-425.2 4392.96,-402.31 881.89,-401.57 905.51,-401.57 929.13,-401.57 1047.24,-401.57 1070.87,-401.57 1094.49,-401.57 1118.11,-401.57 1141.73,-401.57 2622.05,-401.57 2645.67,-401.57 2669.29,-401.57 2763.78,-401.57 2787.4,-401.57 2811.02,-401.57 2834.65,-401.57 2858.27,-401.57 4346.46,-401.57 4370.08,-401.57 4480.32,-401.57 4503.94,-401.57 4527.56,-401.57 4551.18,-401.57 4574.8,-401.57 881.89,-377.95 905.51,-377.95 929.13,-377.95 1047.24,-377.95 1070.87,-377.95 1094.49,-377.95 1118.11,-377.95 1141.73,-377.95 2622.05,-377.95 2645.67,-377.95 2669.29,-377.95 2763.78,-377.95 2787.4,-377.95 2811.02,-377.95 2834.65,-377.95 2858.27,-377.95 4346.46,-377.95 4369.34,-378.69 4393.7,-377.95 4480.32,-377.95 4503.94,-377.95 4527.56,-377.95 4551.18,-377.95 4574.8,-377.95 1511.81,-190.94 1511.81,-165.35 3866.14,78.74 3866.14,110.24 3188.98,183.07 1515.75,190.94 3169.29,194.88 1515.75,214.57 623.12,377.95 645.67,377.95 669.29,377.95 692.91,377.95 803.15,377.95 826.77,377.95 850.39,377.95 2334.65,377.95 2358.27,377.95 2381.89,377.95 2405.51,377.95 2519.69,377.95 2543.31,377.95 2566.93,377.95 4236.22,377.95 4259.84,377.95 4283.46,377.95 4027.56,381.89 4051.18,381.89 4074.8,381.89 4098.43,381.89 4122.05,381.89 623.12,401.57 645.67,401.57 669.29,401.57 692.91,401.57 803.15,401.57 826.77,401.57 850.39,401.57 2334.65,401.57 2358.27,401.57 2381.89,401.57 2405.51,401.57 2519.69,401.57 2543.31,401.57 2566.93,401.57 4236.22,401.57 4259.84,401.57 4283.46,401.57 4027.56,405.51 4051.18,405.51 4074.8,405.51 4098.43,405.51 4122.05,405.51 623.12,425.2 645.67,425.2 669.29,425.2 692.91,425.2 803.15,425.2 826.77,425.2 850.39,425.2 2334.65,425.2 2358.27,425.2 2381.89,425.2 2405.51,425.2 2519.69,425.2 2543.31,425.2 2566.93,425.2 4236.22,425.2 4259.84,425.2 4283.46,425.2 4027.56,429.13 4051.18,429.13 4074.8,429.13 4098.43,429.13 4122.05,429.13 4220.47,686.1 2421.26,696.85 4023.62,700.79 4118.11,700.79 4220.47,708.66 2614.17,716.54 2421.26,720.47 2515.75,720.47 4023.62,724.41 4118.11,724.41 4220.47,732.28 905.51,736.22 2614.17,740.16 2421.26,744.09 2515.75,744.09 704.72,748.03 803.15,748.03 4023.62,748.03 4118.11,748.03 4220.47,755.91 905.51,759.84 2614.17,763.78 2421.26,767.72 2515.75,767.72 704.72,771.65 803.15,771.65 4023.62,771.65 4118.11,771.65 4220.47,779.53 905.51,783.46 2614.17,787.4 2421.26,791.34 2515.75,791.34 4716.54,791.34 4740.16,791.34 4763.78,791.34 4787.4,791.34 4811.02,791.34 4834.65,791.34 4858.27,791.34 4881.89,791.34 4905.51,791.34 4929.13,791.34 4952.76,791.34 4976.38,791.34 5000,791.34 704.72,795.28 803.15,795.28 4023.62,795.28 4118.11,795.28 4220.47,803.15 905.51,807.09 2614.17,811.02 2421.26,814.96 2515.75,814.96 4740.16,814.96 4763.78,814.96 4787.4,814.96 4811.02,814.96 4834.65,814.96 4858.27,814.96 4881.89,814.96 4905.51,814.96 4929.13,814.96 4952.76,814.96 4976.38,814.96 5000,814.96 704.72,818.9 803.15,818.9 4023.62,818.9 4118.11,818.9 3102.36,830.71 3125.98,830.71 3149.61,830.71 3173.23,830.71 3196.85,830.71 3220.47,830.71 3244.09,830.71 3267.72,830.71 3291.34,830.71 3314.96,830.71 3338.58,830.71 3362.2,830.71 1385.83,834.65 1409.45,834.65 1433.07,834.65 1456.69,834.65 1480.31,834.65 1503.94,834.65 1527.56,834.65 1551.18,834.65 1574.8,834.65 1598.43,834.65 1622.05,834.65 1645.67,834.65 2421.26,838.58 2515.75,838.58 704.72,842.52 803.15,842.52 4023.62,842.52 4118.11,842.52 2421.26,862.2 2515.75,862.2 704.72,866.14 803.15,866.14 4023.62,866.14 4118.11,866.14 2421.26,885.83 2515.75,885.83 704.72,889.76 803.15,889.76 4023.62,889.76 4118.11,889.76 2421.26,909.45 2515.75,909.45 704.72,913.39 803.15,913.39 4023.62,913.39 4118.11,913.39 2421.26,933.07 2515.75,933.07 704.72,937.01 803.15,937.01 4023.62,937.01 4118.11,937.01 2421.26,956.69 2515.75,956.69 704.72,960.63 803.15,960.63 4023.62,960.63 4118.11,960.63 2421.26,980.32 2515.75,980.32 704.72,984.25 803.15,984.25 4023.62,984.25 4118.11,984.25 2421.26,1003.94 2515.75,1003.94 704.72,1007.87 803.15,1007.87 4023.62,1007.87 4118.11,1007.87 2421.26,1027.56 2515.75,1027.56 704.72,1031.5 803.15,1031.5 4023.62,1031.5 4118.11,1031.5
I_1V5: C105.1 IC5.1 R129.2 TP15.1 | length 391.4
  Top Layer w4: TP15.1@3106.3,244.09 3185.04,322.83 3267.72,322.83 v1(3287.4,303.15)
  Top Layer w11.81: IC5.1@3267.72,224.41 3267.72,259.84 3287.4,279.53 v1(3287.4,303.15)
  Bottom Layer w11.81: v1(3287.4,303.15) C105.1@3318.9,303.15 R129.2@3318.9,354.33
I_2V5RX: C152.1 IC7.1 R131.2 TP16.1 | length 185.6
  Top Layer w7.87: IC7.1@1535.43,-216.54 v1(1535.43,-240.16) 1535.43,-263.78 TP16.1@1559.06,-287.4
  Bottom Layer w19.68: R131.2@1437.01,-224.41 1519.69,-224.41 v1(1535.43,-240.16)
I_2V5TX: C106.1 IC6.1 R130.2 TP17.1 | length 185.6
  Top Layer w7.87: IC6.1@1535.43,165.35 v1(1535.43,141.73) 1535.43,118.11 TP17.1@1559.06,94.49
  Bottom Layer w19.68: R130.2@1437.01,157.48 1519.69,157.48 v1(1535.43,141.73)
IC1_SCL: IC1.U2 P1.2 R110.1 | length 1218.1
  Top Layer w4: v1(2047.24,-350.39) 2047.24,-177.16 IC1.U2@2066.93,-157.48 ; P1.2@2684.25,-954.72 2685.04,-953.94 v1(2685.04,-850.39)
  Bottom Layer w4: v1(2047.24,-350.39) 2066.93,-350.39 2122.05,-405.51 R110.1@2192.91,-405.51 2192.91,-476.38 2537.4,-820.87 2537.4,-834.65 2574.8,-872.05 2663.39,-872.05 v1(2685.04,-850.39)
IC1_SDA: IC1.U3 P1.4 R109.1 | length 1063.7
  Top Layer w4: v1(2086.61,-338.58) 2086.61,-192.91 IC1.U3@2086.61,-157.48 ; P1.4@2584.25,-954.72 2584.65,-954.33 v1(2584.65,-850.39)
  Bottom Layer w4: v1(2086.61,-338.58) 2129.92,-381.89 2216.54,-381.89 2240.16,-405.51 R109.1@2255.91,-405.51 2255.91,-496.06 2584.65,-824.8 v1(2584.65,-850.39)
LD_DIS: IC1.L6 IC2.16 pad.1@1086.61,-39.37 pad.1@2135.83,-29.53 | length 1151.2
  Top Layer w4: IC2.16@1050,-39.37 pad.1@1086.61,-39.37
  Top Layer w5.12: pad.1@2135.83,-29.53 IC1.L6@2145.67,-39.37
  M1 w4: pad.1@1086.61,-39.37 2007.87,-39.37 2051.18,-82.68 2102.36,-82.68 2125.98,-59.06 2125.98,-39.37 pad.1@2135.83,-29.53
LD_RSTN: IC1.M8 IC2.14 pad.1@1102.36,-55.12 pad.1@2175.2,-49.21 | length 1174.2
  Top Layer w4: IC2.14@1050,-55.12 pad.1@1102.36,-55.12
  Top Layer w5.12: pad.1@2175.2,-49.21 IC1.M8@2185.04,-59.05
  M1 w4: pad.1@1102.36,-55.12 2003.94,-55.12 2043.31,-94.49 2129.92,-94.49 pad.1@2175.2,-49.21
LV_RB: P11.3 P11.4 R129.1 R130.1 R131.1 R142.1 R228.2 TP5.1 | length 4440.2
  Top Layer w4: TP5.1@1448.82,-375.98 1454.72,-375.98 1507.87,-322.83
  Top Layer w11.81: v1(1362.2,-177.17) 1507.87,-322.83 1661.42,-322.83 1736.22,-248.03 R142.1@1736.22,-212.6
  Bottom Layer w4.02: R228.2@3543.31,303.15 3543.31,354.33
  Bottom Layer w19.68: v1@1363.19,-173.23 1367.13,-177.17 R131.1@1437.01,-177.17 ; 1363.19,207.68 1366.14,204.72 R130.1@1437.01,204.72
  Bottom Layer w39.37: v1(86.61,350.39) v1(86.61,267.72) 1303.15,267.72 1363.19,207.68 v1@1363.19,-173.23 ; R129.1@3366.14,354.33 3543.31,354.33 3787.4,354.33 3874.02,267.72 4429.13,267.72 4641.73,480.32 v1(5051.18,480.32) v1(5051.18,397.64)
  other v1: 86.61,295.28 86.61,322.83 5051.18,425.2 5051.18,452.76 2322.83,933.07 2322.83,956.69 2322.83,980.32 2322.83,1003.94 2322.83,1027.56
M1SCL: IC1.E6 P6.20 P8.20 P10.20 pad.1@1015.75,-330.71 pad.1@2156.48,88.58 R103.1 | length 6580.9
  Top Layer w4.02: v1(2720.47,-444.88) 2720.47,-445.4 2732.28,-457.21 v1(2732.28,-632.79)
  Top Layer w5.12: IC1.E6@2145.67,78.74 2155.51,88.58 pad.1@2156.48,88.58
  M1 w4.02: pad.1@2156.48,88.58 2142.7,74.8 2059.06,74.8 2047.24,86.61 2027.56,86.61 1988.19,47.24 1082.68,47.24 1015.75,-19.69 pad.1@1015.75,-330.71 704.72,-330.71 669.29,-366.14 669.29,-594.49 708.66,-633.86 2731.21,-633.86 v1(2732.28,-632.79) ; v1@2732.28,-633.86 3354.33,-633.86 3370.08,-618.11 3531.5,-618.11 3547.24,-633.86 4409.45,-633.86 4448.82,-594.49 4448.82,-429.13 v1(4437.01,-417.32)
  Bottom Layer w4: P6.20@1015.75,-472.44 pad.1@1015.75,-330.71 R103.1@1051.18,-330.71
  Bottom Layer w4.02: v1(2720.47,-444.88) 2732.28,-456.69 P8.20@2732.28,-472.44 ; v1(4437.01,-417.32) 4448.82,-429.13 P10.20@4448.82,-472.44
M1SDA: IC1.F6 P6.18 P8.18 P10.18 pad.1@1051.18,-267.72 pad.1@2155.51,49.21 R104.1 | length 6560
  Top Layer w4.02: v1(2712.6,-602.36) 2712.6,-519.68 2700.79,-507.87 2700.79,-429.13 v1(2712.6,-417.32)
  Top Layer w5.12: IC1.F6@2145.67,59.06 pad.1@2155.51,49.21
  M1 w4.02: pad.1@2155.51,49.21 2141.73,62.99 2051.18,62.99 2011.81,23.62 1157.48,23.62 1137.8,3.94 1074.8,3.94 1051.18,-19.69 pad.1@1051.18,-267.72 1051.18,-330.71 1027.56,-354.33 704.72,-354.33 685.04,-374.02 685.04,-586.61 720.47,-622.05 2692.91,-622.05 v1(2712.6,-602.36) 2767.72,-602.36 2787.4,-622.05 3346.46,-622.05 3362.2,-606.3 3543.31,-606.3 3559.06,-622.05 4389.76,-622.05 4425.2,-586.61 v1(4425.2,-440.94)
  Bottom Layer w4.02: P6.18@984.25,-472.44 984.25,-334.65 pad.1@1051.18,-267.72 R104.1@1051.18,-240.16 ; P8.18@2700.79,-472.44 2700.79,-429.13 v1(2712.6,-417.32) ; P10.18@4417.32,-472.44 4417.32,-448.82 v1(4425.2,-440.94)
M2SCL: IC1.E5 IC2.10 IC4.U2 pad.1@1118.11,-283.46 pad.1@2136.79,88.58 pad.1@2805.12,-147.64 R105.1 | length 2400.1
  Top Layer w4: IC2.10@1050,-86.61 1011.81,-86.61 1000,-98.43 1000,-165.35 pad.1@1118.11,-283.46
  Top Layer w5.12: IC1.E5@2125.98,78.74 2135.83,88.58 pad.1@2136.79,88.58 ; pad.1@2805.12,-147.64 IC4.U2@2814.96,-157.48
  Bottom Layer w4: pad.1@1118.11,-283.46 1228.35,-283.46 ; R105.1@1228.35,-342.52 1228.35,-283.46 ; pad.1@2805.12,-147.64 2787.4,-165.35 2555.12,-165.35 2314.96,74.8 2150.57,74.8 pad.1@2136.79,88.58 2123.01,74.8 2059.06,74.8 2047.24,86.61 2027.56,86.61 1940.94,0 1771.65,0 1669.29,-102.36 1669.29,-204.72 1590.55,-283.46 1228.35,-283.46
M2SDA: IC1.F5 IC2.8 IC4.U3 pad.1@2135.86,48.28 pad.1@2824.8,-147.64 R106.1 | length 2371.9
  Top Layer w4: IC2.8@1050,-102.36 1019.69,-102.36 1011.81,-110.24 1011.81,-153.54 1165.35,-307.09 v1(1279.53,-307.09)
  Top Layer w5.12: IC1.F5@2125.98,59.06 2135.86,49.18 pad.1@2135.86,48.28 ; pad.1@2824.8,-147.64 IC4.U3@2834.65,-157.48
  Bottom Layer w4: R106.1@1279.53,-342.52 v1(1279.53,-307.09) 1610.24,-307.09 1688.98,-228.35 1688.98,-110.24 1775.59,-23.62 1964.57,-23.62 2051.18,62.99 2121.14,62.99 pad.1@2135.86,48.28 2150.57,62.99 2311.02,62.99 2551.18,-177.17 2795.28,-177.17 pad.1@2824.8,-147.64
NetC107_1: C107.1 R111.2 | length 62.3
  Bottom Layer w11.81: R111.2@3314.96,188.98 3314.96,212.6 3322.83,220.47 C107.1@3322.83,248.03
NetC108_1: C108.1 R114.1 | length 60.7
  Bottom Layer w19.68: C108.1@1476.38,334.65 1480.31,338.58 R114.1@1535.43,338.58
NetC155_1: C155.1 R128.2 | length 51.2
  Bottom Layer w11.81: C155.1@3212.6,47.24 R128.2@3212.6,98.43
NetC169_1: C169.1 R125.1 | length 63.2
  Bottom Layer w19.68: C169.1@1483.27,-36.42 C169.1@1480.31,-39.37 R125.1@1539.37,-39.37
NetD1_1: D1.1 R142.2 | length 71.1
  Top Layer w5: D1.1@1783.46,-161.42 D1.1@1791.34,-153.54
  Top Layer w11.81: R142.2@1736.22,-165.35 1748.03,-153.54 D1.1@1791.34,-153.54
NetD1_2: D1.2 Q1.1 | length 57.7
  Top Layer w11.81: D1.2@1791.34,-212.6 1826.77,-212.6 Q1.1@1842.52,-196.85
NetIC1_A2: IC1.A2 IC2.32 R144.1 | length 1470.9
  Top Layer w4: IC2.32@1050,86.61 1088.58,86.61 1104.33,102.36 1104.33,159.45 1271.65,326.77 1698.82,326.77 1700.79,326.77 ; R144.1@1673.23,96.46 1673.23,104.33 1698.82,129.92 1698.82,324.8 1700.79,326.77 ; IC1.A2@2066.93,157.48 2066.93,173.23 1913.39,326.77 1700.79,326.77
NetIC1_G1: IC1.G1 IC2.15 | length 925.1
  Top Layer w4.72: IC2.15@1154.72,-39.37 1187.6,-39.37 1195.47,-31.5 1228.35,-31.5 1289.37,29.53 2037.4,29.53 IC1.G1@2047.24,39.37
NetIC1_H1: IC1.H1 IC2.13 | length 923.5
  Top Layer w4.72: IC2.13@1154.72,-55.12 1244.09,-55.12 1309.06,9.84 2037.4,9.84 IC1.H1@2047.24,19.69
NetIC1_L1: IC1.L1 IC2.9 | length 921.9
  Top Layer w4.72: IC2.9@1154.72,-86.61 1251.97,-86.61 1299.21,-39.37 1358.27,-39.37 1370.08,-27.56 1433.07,-27.56 1444.88,-39.37 IC1.L1@2047.24,-39.37
NetIC1_M1: IC1.M1 IC2.7 | length 920.2
  Top Layer w4.72: IC2.7@1154.72,-102.36 1188.98,-102.36 1200.79,-114.17 1263.78,-114.17 1318.9,-59.05 IC1.M1@2047.24,-59.05
NetIC1_P2: IC1.P2 IC4.P2 JMP2.2 pad.1@2824.8,-108.27 R102.2 | length 1286.7
  Top Layer w3: v1(2007.87,-88.58) 2057.09,-88.58 IC1.P2@2066.93,-98.42
  Top Layer w5.12: IC4.P2@2814.96,-98.43 pad.1@2824.8,-108.27
  Bottom Layer w4: 1797.24,-80.09 1805.97,-80.09 1837.24,-80.09 1858.27,-59.06 1940.94,-59.06 1948.82,-66.93 R102.2@1948.82,-86.61 1950.79,-88.58 v1(2007.87,-88.58) 2007.87,-127.95 2072.83,-192.91 2803.15,-192.91 2838.58,-157.48 2838.58,-122.05 pad.1@2824.8,-108.27
NetIC1_P3: IC1.P3 IC4.P3 JMP1.2 pad.1@2844.49,-108.27 R101.1 | length 1366.4
  Top Layer w3: v1(1988.19,-108.27) 2017.72,-108.27 2076.77,-108.27 IC1.P3@2086.61,-98.42
  Top Layer w5.12: IC4.P3@2834.65,-98.43 pad.1@2844.49,-108.27
  Bottom Layer w4: 1793.31,-200.16 1799.84,-206.69 1948.82,-206.69 ; v1(1988.19,-108.27) 1950.79,-145.67 R101.1@1948.82,-145.67 1948.82,-206.69 ; pad.1@2844.49,-108.27 2850.39,-114.17 2850.39,-161.42 2805.12,-206.69 1948.82,-206.69
NetIC1_R16: IC1.R16 IC3.L13 pad.1@2352.36,-127.95 pad.1@3480.32,-157.48 | length 1272.6
  Top Layer w5.12: IC1.R16@2342.52,-118.11 pad.1@2352.36,-127.95 ; IC3.L13@3464.57,-173.23 pad.1@3480.32,-157.48
  M1 w4.72: pad.1@2352.36,-127.95 2374.01,-106.3 2470.47,-106.3 2557.09,-192.91 3236.22,-192.91 3295.28,-251.97 3385.83,-251.97 pad.1@3480.32,-157.48
NetIC1_R17: IC1.R17 IC3.L14 pad.1@2372.05,-127.95 pad.1@3480.32,-188.98 | length 1270.8
  Top Layer w5.12: IC1.R17@2362.2,-118.11 pad.1@2372.05,-127.95 ; IC3.L14@3464.57,-204.72 pad.1@3480.32,-188.98
  M1 w4.72: pad.1@2372.05,-127.95 2460.63,-127.95 2549.21,-216.54 3094.49,-216.54 3153.54,-275.59 3177.17,-275.59 3212.6,-240.16 3244.09,-240.16 3279.53,-275.59 3393.7,-275.59 pad.1@3480.32,-188.98
NetIC1_T16: IC1.T16 IC3.K13 pad.1@2352.36,-147.64 pad.1@3511.8,-188.98 | length 1304.1
  Top Layer w5.12: IC1.T16@2342.52,-137.79 pad.1@2352.36,-147.64 ; IC3.K13@3496.06,-173.23 pad.1@3511.8,-188.98
  M1 w4.72: pad.1@2352.36,-147.64 2446.85,-147.64 2535.43,-236.22 3070.87,-236.22 3133.86,-299.21 3401.57,-299.21 pad.1@3511.8,-188.98
NetIC1_T17: IC1.T17 IC3.J13 pad.1@2475.39,-231.3 pad.1@3543.3,-188.98 | length 1404.4
  Top Layer w4.72: IC1.T17@2362.2,-137.79 2370.08,-145.67 2389.76,-145.67 pad.1@2475.39,-231.3
  Top Layer w5.12: IC3.J13@3527.56,-173.23 pad.1@3543.3,-188.98
  M1 w4.72: pad.1@2475.39,-231.3 2475.22,-231.3 2465.55,-221.63 2519.52,-275.59 3027.56,-275.59 3102.36,-350.39 3413.39,-350.39 3527.56,-236.22 3527.56,-204.72 pad.1@3543.3,-188.98
NetIC1_U16: IC1.U16 IC3.K14 pad.1@2352.36,-167.32 pad.1@3511.81,-220.47 | length 1305.7
  Top Layer w5.12: IC1.U16@2342.52,-157.48 pad.1@2352.36,-167.32 ; IC3.K14@3496.06,-204.72 pad.1@3511.81,-220.47
  M1 w4.72: pad.1@2352.36,-167.32 2438.98,-167.32 2527.56,-255.91 3051.18,-255.91 3122.05,-326.77 3405.51,-326.77 pad.1@3511.81,-220.47
NetIC1_U17: IC1.U17 IC3.J14 pad.1@2436.02,-231.3 pad.1@3543.31,-220.47 | length 1405.1
  Top Layer w4.72: IC1.U17@2362.2,-157.48 pad.1@2436.02,-231.3
  Top Layer w5.12: IC3.J14@3527.56,-204.72 pad.1@3543.31,-220.47
  M1 w4.72: pad.1@2436.02,-231.3 2500,-295.28 3007.87,-295.28 3086.61,-374.02 3472.44,-374.02 3543.31,-303.15 pad.1@3543.31,-220.47
NetIC2_19: IC2.19 IC4.H1 pad.1@2779.53,19.68 | length 1718.8
  Top Layer w4.72: IC2.19@1154.72,-7.87 v1(1208.66,-7.87)
  Top Layer w5.12: pad.1@2779.53,19.68 IC4.H1@2795.28,19.68
  M2 w4.72: v1(1208.66,-7.87) 1440.94,-7.87 1956.69,-7.87 2037.4,-88.58 2372.05,-88.58 2409.45,-51.18 2708.66,-51.18 pad.1@2779.53,19.68
NetIC2_21: IC2.21 IC4.G1 pad.1@2779.53,39.37 | length 1718.8
  Top Layer w4.72: IC2.21@1154.72,7.87 1188.98,7.87 1259.84,78.74 v1(1299.21,78.74)
  Top Layer w5.12: pad.1@2779.53,39.37 IC4.G1@2795.28,39.37
  M2 w4.72: v1(1299.21,78.74) 1427.17,78.74 1476.38,29.53 2017.72,29.53 2057.09,68.9 2750,68.9 pad.1@2779.53,39.37
NetIC5_4: IC5.4 R126.1 R127.2 | length 74.8
  Top Layer w4: IC5.4@3208.66,224.41 v1(3208.66,244.09)
  Bottom Layer w4: R127.2@3208.66,216.54 v1(3208.66,244.09) R126.1@3208.66,271.65
NetIC5_5: IC5.5 R112.1 R113.2 | length 107.9
  Top Layer w4: IC5.5@3208.66,153.54 3208.66,129.92 3212.6,125.98 R112.1@3212.6,47.24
